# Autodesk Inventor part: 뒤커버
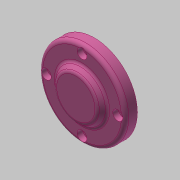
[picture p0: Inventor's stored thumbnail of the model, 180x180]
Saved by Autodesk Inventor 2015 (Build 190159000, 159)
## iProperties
Created: 2017-08
Part Number: 뒤커버
Material: 알루미늄 6061
Document SubType Name: Modeling
Designer: mduedu
Density: 1 g/cm^3
Appearance: 분홍색
Author: mduedu
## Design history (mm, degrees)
sketch "스케치1"
  geometry: C1 r 35 at (0, 0); 1 further point
  constraints: 1 centre point, 1 coincident
  dimensions: "d0" = 70 diameter of C1
extrude "돌출1" new body sketch "스케치1" distance "d1" = 10; taper "d2" = 0 deg
sketch "스케치2"
  geometry: C1 r 21 at (0, 0); 1 further point
  constraints: 1 centre point, 1 coincident
  dimensions: "d3" = 42 diameter of C1
node "작업 평면1"
sketch "스케치3"
  geometry: C1 r 17 at (0, 0); 1 further point
  constraints: 1 centre point, 1 coincident
  dimensions: "d5" = 34 diameter of C1
feature "로프트1" sketch "스케치3" dims "d6" = 0, "d7" = 90 deg, "d8" = 0, "d9" = 90 deg
sketch "스케치4"
  geometry: C1 r 24 at (0, 0); 1 further point
  constraints: 1 centre point, 1 coincident
  dimensions: "d65" = 48 diameter of C1
extrude "돌출2" join sketch "스케치4" distance "d10" = 8; taper "d11" = 0 deg
hole "구멍1" diameter "d14" = 40; stored, may be unused: countersink angle "d18" = 90 deg, drill point angle "d20" = 0 deg; dims "d15" = 6, "d16" = 4, "d17" = 2, "d19" = 12, "d66" = 10, "d67" = 10
hole "구멍2" diameter "d23" = 34; stored, may be unused: countersink angle "d27" = 90 deg, drill point angle "d29" = 0 deg; dims "d24" = 6, "d25" = 4, "d26" = 2, "d28" = 6, "d62" = 10, "d63" = 10
chamfer "모따기1" distance "d39" = 1; stored, may be unused: second distance "d40" = 2, angle "d41" = 45 deg
fillet "모깎기1" dims "d42" = 0.3
fillet "모깎기2" dims "d43" = 3
sketch "스케치5" dims "d44" = 58
  geometry: 6 further points
  constraints: 2 vertical alignment, 1 coincident, 7 other
  dimensions: "d47" = 360 deg dimension on point (0, 0) point (0, 29) (derived)
sketch "스케치6" dims "d64" = 58 (derived)
  geometry: 6 further points
  constraints: 1 coincident, 1 vertical alignment, 6 other
hole "구멍4" sketch "스케치6" at (0, 29), (-29, 0), (29, 0), (0, -29) diameter "d49" = 4.5; stored, may be unused: countersink angle "d53" = 90 deg, drill point angle "d55" = 0 deg; dims "d50" = 6, "d51" = 8, "d52" = 4.6, "d54" = 8
fillet "모깎기3" dims "d56" = 3
fillet "모깎기4" dims "d57" = 3
fillet "모깎기5" dims "d58" = 3
node "솔리드1"
other parameters: "d4" = 5
